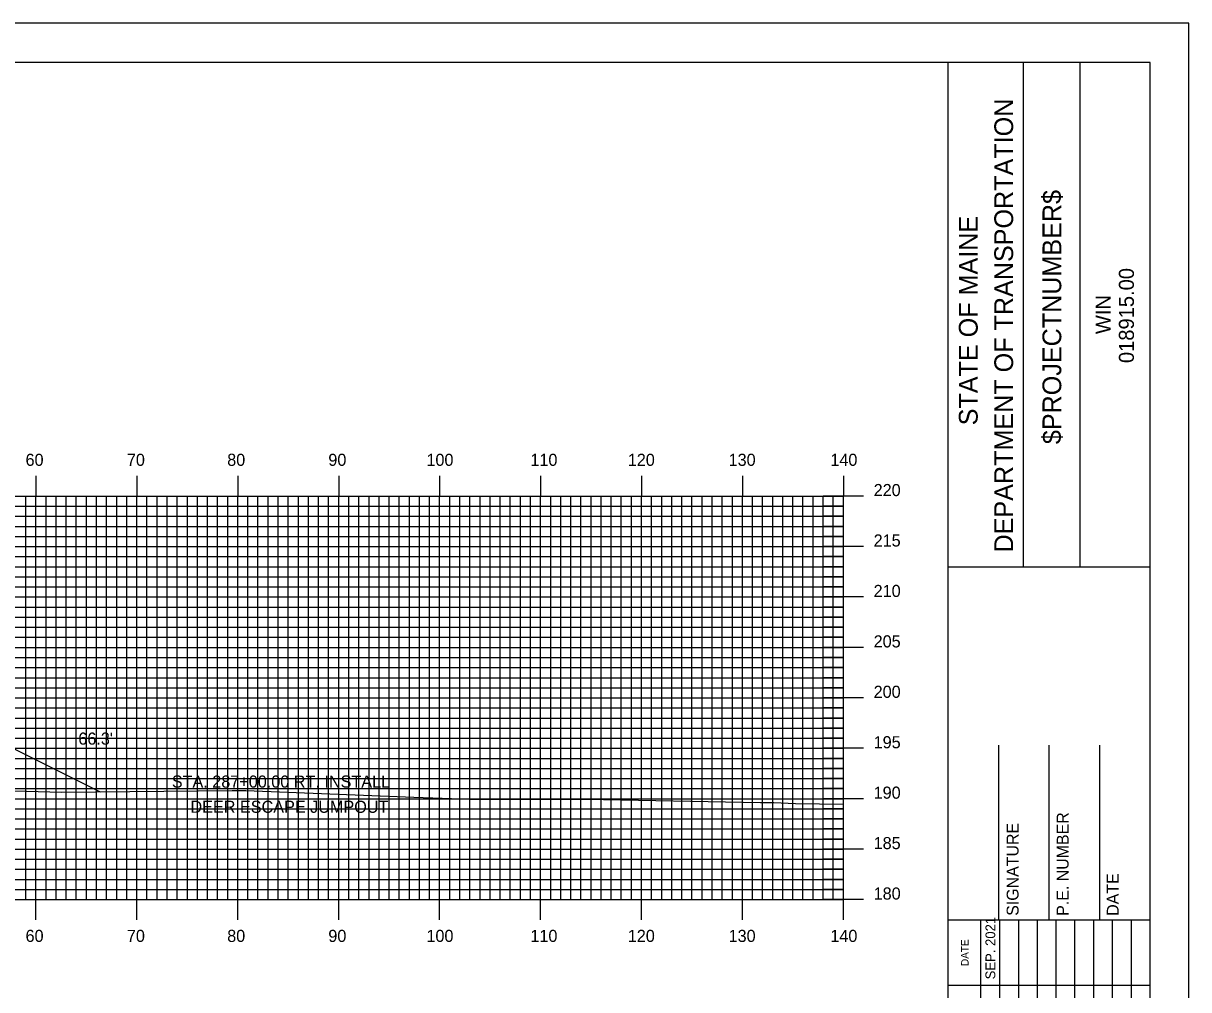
# Model space of a CAD drawing. Extents: x 1812554 to 1812897, y 442591 to 442811.
# Drawn here: x 1812778.7 to 1812894.2, y 442714.7 to 442810.5 of the extents above; entities that cross this region are included whole.
import ezdxf

# ---------------------------------------------------------------- set-up
doc = ezdxf.new("R2010")
doc.units = 0
for name, color, linetype in [('BORDER', 7, 'Continuous'), ('D_Roadway_Centerline', 7, 'Continuous'), ('D_Roadway_SlopeLines', 7, 'Continuous'), ('D_Text_Standard', 7, 'Continuous'), ('H_V ANNOTATION', 7, 'Continuous'), ('MAJOR', 7, 'Continuous'), ('MINOR', 7, 'Continuous'), ('PLOT BOUNDARY', 7, 'Continuous'), ('S_Roadway_Centerline', 7, 'Continuous')]:
    doc.layers.add(name, color=color, linetype=linetype)

msp = doc.modelspace()

# ---------------------------------------------------------------- linework, layer by layer
at = {"layer": 'BORDER'}
for p, q in [((1812870.34, 442596.67), (1812870.34, 442806.67)), ((1812877.8, 442756.66), (1812877.8, 442806.66)), ((1812883.39, 442756.66), (1812883.39, 442806.66)), ((1812870.34, 442756.65), (1812890.34, 442756.65)), ((1812875.34, 442721.67), (1812875.34, 442738.97)), ((1812880.34, 442721.67), (1812880.34, 442738.97)), ((1812885.34, 442721.67), (1812885.34, 442738.97)), ((1812870.34, 442721.67), (1812890.34, 442721.67))]:
    msp.add_line(p, q, dxfattribs=at)
msp.add_lwpolyline([(1812570.34, 442596.67), (1812890.34, 442596.67), (1812890.34, 442806.67), (1812570.34, 442806.67)], close=True, dxfattribs=at)
for points in [[(1812873.57, 442715.17), (1812873.57, 442721.67)], [(1812875.44, 442686.68), (1812875.44, 442721.67)], [(1812877.3, 442721.67), (1812877.3, 442686.68)], [(1812879.16, 442686.68), (1812879.16, 442721.67)], [(1812881.03, 442686.68), (1812881.03, 442721.67)], [(1812882.89, 442686.68), (1812882.89, 442721.67)], [(1812884.75, 442686.68), (1812884.75, 442721.67)], [(1812886.62, 442686.68), (1812886.62, 442721.67)], [(1812888.48, 442686.68), (1812888.48, 442721.67)], [(1812873.57, 442686.68), (1812873.57, 442720.26)], [(1812870.34, 442715.17), (1812890.34, 442715.17)]]:
    msp.add_lwpolyline(points, dxfattribs=at)
at = {"layer": 'D_Roadway_Centerline'}
msp.add_lwpolyline([(1812657.88, 442737.96), (1812691.73, 442754.88), (1812696.94, 442757.49), (1812699.94, 442757.55), (1812707.94, 442757.71), (1812719.94, 442757.13), (1812731.94, 442756.55), (1812739.94, 442756.17), (1812742.94, 442756.03), (1812748.47, 442753.26), (1812786.29, 442734.35)], dxfattribs=at)
at = {"layer": 'D_Roadway_SlopeLines'}
msp.add_lwpolyline([(1812742.94, 442756.03), (1812786.29, 442734.35)], dxfattribs=at)
at = {"layer": 'MAJOR'}
for p, q in [((1812779.94, 442765.67), (1812779.94, 442763.67)), ((1812789.94, 442765.67), (1812789.94, 442763.67)), ((1812799.94, 442765.67), (1812799.94, 442763.67)), ((1812809.94, 442765.67), (1812809.94, 442763.67)), ((1812819.94, 442765.67), (1812819.94, 442763.67)), ((1812829.94, 442765.67), (1812829.94, 442763.67)), ((1812839.94, 442765.67), (1812839.94, 442763.67)), ((1812849.94, 442765.67), (1812849.94, 442763.67)), ((1812859.94, 442765.67), (1812859.94, 442763.67)), ((1812579.94, 442763.67), (1812859.94, 442763.67)), ((1812579.94, 442763.67), (1812859.94, 442763.67)), ((1812779.94, 442723.67), (1812779.94, 442763.67)), ((1812789.94, 442723.67), (1812789.94, 442763.67)), ((1812799.94, 442723.67), (1812799.94, 442763.67)), ((1812809.94, 442723.67), (1812809.94, 442763.67)), ((1812819.94, 442723.67), (1812819.94, 442763.67)), ((1812829.94, 442723.67), (1812829.94, 442763.67)), ((1812839.94, 442723.67), (1812839.94, 442763.67)), ((1812849.94, 442723.67), (1812849.94, 442763.67)), ((1812861.95, 442763.67), (1812857.94, 442763.67)), ((1812859.94, 442723.67), (1812859.94, 442763.67)), ((1812859.94, 442723.67), (1812859.94, 442763.67)), ((1812579.94, 442758.67), (1812859.94, 442758.67)), ((1812861.95, 442758.67), (1812857.94, 442758.67)), ((1812579.94, 442753.67), (1812859.94, 442753.67)), ((1812861.95, 442753.67), (1812857.94, 442753.67)), ((1812579.94, 442748.67), (1812859.94, 442748.67)), ((1812861.95, 442748.67), (1812857.94, 442748.67)), ((1812579.94, 442743.67), (1812859.94, 442743.67)), ((1812861.95, 442743.67), (1812857.94, 442743.67)), ((1812579.94, 442738.67), (1812859.94, 442738.67)), ((1812861.95, 442738.67), (1812857.94, 442738.67)), ((1812579.94, 442733.67), (1812859.94, 442733.67)), ((1812861.95, 442733.67), (1812857.94, 442733.67)), ((1812579.94, 442728.67), (1812859.94, 442728.67)), ((1812861.95, 442728.67), (1812857.94, 442728.67)), ((1812579.94, 442723.67), (1812859.94, 442723.67)), ((1812579.94, 442723.67), (1812859.94, 442723.67)), ((1812779.94, 442721.66), (1812779.94, 442723.67)), ((1812789.94, 442721.66), (1812789.94, 442723.67)), ((1812799.94, 442721.66), (1812799.94, 442723.67)), ((1812809.94, 442721.66), (1812809.94, 442723.67)), ((1812819.94, 442721.66), (1812819.94, 442723.67)), ((1812829.94, 442721.66), (1812829.94, 442723.67)), ((1812839.94, 442721.66), (1812839.94, 442723.67)), ((1812849.94, 442721.66), (1812849.94, 442723.67)), ((1812861.95, 442723.67), (1812857.94, 442723.67)), ((1812859.94, 442721.66), (1812859.94, 442723.67))]:
    msp.add_line(p, q, dxfattribs=at)
at = {"layer": 'MINOR'}
for p, q in [((1812778.94, 442723.67), (1812778.94, 442763.67)), ((1812780.94, 442723.67), (1812780.94, 442763.67)), ((1812781.94, 442723.67), (1812781.94, 442763.67)), ((1812782.94, 442723.67), (1812782.94, 442763.67)), ((1812783.94, 442723.67), (1812783.94, 442763.67)), ((1812784.94, 442723.67), (1812784.94, 442763.67)), ((1812785.94, 442723.67), (1812785.94, 442763.67)), ((1812786.94, 442723.67), (1812786.94, 442763.67)), ((1812787.94, 442723.67), (1812787.94, 442763.67)), ((1812788.94, 442723.67), (1812788.94, 442763.67)), ((1812790.94, 442723.67), (1812790.94, 442763.67)), ((1812791.94, 442723.67), (1812791.94, 442763.67)), ((1812792.94, 442723.67), (1812792.94, 442763.67)), ((1812793.94, 442723.67), (1812793.94, 442763.67)), ((1812794.94, 442723.67), (1812794.94, 442763.67)), ((1812795.94, 442723.67), (1812795.94, 442763.67)), ((1812796.94, 442723.67), (1812796.94, 442763.67)), ((1812797.94, 442723.67), (1812797.94, 442763.67)), ((1812798.94, 442723.67), (1812798.94, 442763.67)), ((1812800.94, 442723.67), (1812800.94, 442763.67)), ((1812801.94, 442723.67), (1812801.94, 442763.67)), ((1812802.94, 442723.67), (1812802.94, 442763.67)), ((1812803.94, 442723.67), (1812803.94, 442763.67)), ((1812804.94, 442723.67), (1812804.94, 442763.67)), ((1812805.94, 442723.67), (1812805.94, 442763.67)), ((1812806.94, 442723.67), (1812806.94, 442763.67)), ((1812807.94, 442723.67), (1812807.94, 442763.67)), ((1812808.94, 442723.67), (1812808.94, 442763.67)), ((1812810.94, 442723.67), (1812810.94, 442763.67)), ((1812811.94, 442723.67), (1812811.94, 442763.67)), ((1812812.94, 442723.67), (1812812.94, 442763.67)), ((1812813.94, 442723.67), (1812813.94, 442763.67)), ((1812814.94, 442723.67), (1812814.94, 442763.67)), ((1812815.94, 442723.67), (1812815.94, 442763.67)), ((1812816.94, 442723.67), (1812816.94, 442763.67)), ((1812817.94, 442723.67), (1812817.94, 442763.67)), ((1812818.94, 442723.67), (1812818.94, 442763.67)), ((1812820.94, 442723.67), (1812820.94, 442763.67)), ((1812821.94, 442723.67), (1812821.94, 442763.67)), ((1812822.94, 442723.67), (1812822.94, 442763.67)), ((1812823.94, 442723.67), (1812823.94, 442763.67)), ((1812824.94, 442723.67), (1812824.94, 442763.67)), ((1812825.94, 442723.67), (1812825.94, 442763.67)), ((1812826.94, 442723.67), (1812826.94, 442763.67)), ((1812827.94, 442723.67), (1812827.94, 442763.67)), ((1812828.94, 442723.67), (1812828.94, 442763.67)), ((1812830.94, 442723.67), (1812830.94, 442763.67)), ((1812831.94, 442723.67), (1812831.94, 442763.67)), ((1812832.94, 442723.67), (1812832.94, 442763.67)), ((1812833.94, 442723.67), (1812833.94, 442763.67)), ((1812834.94, 442723.67), (1812834.94, 442763.67)), ((1812835.94, 442723.67), (1812835.94, 442763.67)), ((1812836.94, 442723.67), (1812836.94, 442763.67)), ((1812837.94, 442723.67), (1812837.94, 442763.67)), ((1812838.94, 442723.67), (1812838.94, 442763.67)), ((1812840.94, 442723.67), (1812840.94, 442763.67)), ((1812841.94, 442723.67), (1812841.94, 442763.67)), ((1812842.94, 442723.67), (1812842.94, 442763.67)), ((1812843.94, 442723.67), (1812843.94, 442763.67)), ((1812844.94, 442723.67), (1812844.94, 442763.67)), ((1812845.94, 442723.67), (1812845.94, 442763.67)), ((1812846.94, 442723.67), (1812846.94, 442763.67)), ((1812847.94, 442723.67), (1812847.94, 442763.67)), ((1812848.94, 442723.67), (1812848.94, 442763.67)), ((1812850.94, 442723.67), (1812850.94, 442763.67)), ((1812851.94, 442723.67), (1812851.94, 442763.67)), ((1812852.94, 442723.67), (1812852.94, 442763.67)), ((1812853.94, 442723.67), (1812853.94, 442763.67)), ((1812854.94, 442723.67), (1812854.94, 442763.67)), ((1812855.94, 442723.67), (1812855.94, 442763.67)), ((1812856.94, 442723.67), (1812856.94, 442763.67)), ((1812857.94, 442723.67), (1812857.94, 442763.67)), ((1812858.94, 442723.67), (1812858.94, 442763.67)), ((1812579.94, 442762.67), (1812859.94, 442762.67)), ((1812859.94, 442762.67), (1812857.94, 442762.67)), ((1812579.94, 442761.67), (1812859.94, 442761.67)), ((1812859.94, 442761.67), (1812857.94, 442761.67)), ((1812579.94, 442760.67), (1812859.94, 442760.67)), ((1812859.94, 442760.67), (1812857.94, 442760.67)), ((1812579.94, 442759.67), (1812859.94, 442759.67)), ((1812859.94, 442759.67), (1812857.94, 442759.67)), ((1812579.94, 442757.67), (1812859.94, 442757.67)), ((1812859.94, 442757.67), (1812857.94, 442757.67)), ((1812579.94, 442756.67), (1812859.94, 442756.67)), ((1812859.94, 442756.67), (1812857.94, 442756.67)), ((1812579.94, 442755.67), (1812859.94, 442755.67)), ((1812859.94, 442755.67), (1812857.94, 442755.67)), ((1812579.94, 442754.67), (1812859.94, 442754.67)), ((1812859.94, 442754.67), (1812857.94, 442754.67)), ((1812579.94, 442752.67), (1812859.94, 442752.67)), ((1812579.94, 442751.67), (1812859.94, 442751.67)), ((1812859.94, 442752.67), (1812857.94, 442752.67)), ((1812859.94, 442751.67), (1812857.94, 442751.67)), ((1812579.94, 442750.67), (1812859.94, 442750.67)), ((1812859.94, 442750.67), (1812857.94, 442750.67)), ((1812579.94, 442749.67), (1812859.94, 442749.67)), ((1812859.94, 442749.67), (1812857.94, 442749.67)), ((1812579.94, 442747.67), (1812859.94, 442747.67)), ((1812859.94, 442747.67), (1812857.94, 442747.67)), ((1812579.94, 442746.67), (1812859.94, 442746.67)), ((1812859.94, 442746.67), (1812857.94, 442746.67)), ((1812579.94, 442745.67), (1812859.94, 442745.67)), ((1812859.94, 442745.67), (1812857.94, 442745.67)), ((1812579.94, 442744.67), (1812859.94, 442744.67)), ((1812859.94, 442744.67), (1812857.94, 442744.67)), ((1812579.94, 442742.67), (1812859.94, 442742.67)), ((1812859.94, 442742.67), (1812857.94, 442742.67)), ((1812579.94, 442741.67), (1812859.94, 442741.67)), ((1812859.94, 442741.67), (1812857.94, 442741.67)), ((1812579.94, 442740.67), (1812859.94, 442740.67)), ((1812859.94, 442740.67), (1812857.94, 442740.67)), ((1812579.94, 442739.67), (1812859.94, 442739.67)), ((1812859.94, 442739.67), (1812857.94, 442739.67)), ((1812579.94, 442737.67), (1812859.94, 442737.67)), ((1812579.94, 442736.67), (1812859.94, 442736.67)), ((1812859.94, 442737.67), (1812857.94, 442737.67)), ((1812859.94, 442736.67), (1812857.94, 442736.67)), ((1812579.94, 442735.67), (1812859.94, 442735.67)), ((1812859.94, 442735.67), (1812857.94, 442735.67)), ((1812579.94, 442734.67), (1812859.94, 442734.67)), ((1812859.94, 442734.67), (1812857.94, 442734.67)), ((1812579.94, 442732.67), (1812859.94, 442732.67)), ((1812859.94, 442732.67), (1812857.94, 442732.67)), ((1812579.94, 442731.67), (1812859.94, 442731.67)), ((1812859.94, 442731.67), (1812857.94, 442731.67)), ((1812579.94, 442730.67), (1812859.94, 442730.67)), ((1812859.94, 442730.67), (1812857.94, 442730.67)), ((1812579.94, 442729.67), (1812859.94, 442729.67)), ((1812859.94, 442729.67), (1812857.94, 442729.67)), ((1812579.94, 442727.67), (1812859.94, 442727.67)), ((1812859.94, 442727.67), (1812857.94, 442727.67)), ((1812579.94, 442726.67), (1812859.94, 442726.67)), ((1812859.94, 442726.67), (1812857.94, 442726.67)), ((1812579.94, 442725.67), (1812859.94, 442725.67)), ((1812859.94, 442725.67), (1812857.94, 442725.67)), ((1812579.94, 442724.67), (1812859.94, 442724.67)), ((1812859.94, 442724.67), (1812857.94, 442724.67))]:
    msp.add_line(p, q, dxfattribs=at)
at = {"layer": 'PLOT BOUNDARY'}
msp.add_lwpolyline([(1812554.16, 442590.55), (1812894.16, 442590.55), (1812894.16, 442810.55), (1812554.16, 442810.55)], close=True, dxfattribs=at)
at = {"layer": 'S_Roadway_Centerline'}
msp.add_lwpolyline([(1812773.23, 442734.57), (1812782.47, 442734.32), (1812799.39, 442734.48), (1812800.25, 442734.49), (1812800.74, 442734.5), (1812817.37, 442733.81), (1812823.91, 442733.58), (1812834.44, 442733.62), (1812851.73, 442733.3), (1812853.06, 442733.28), (1812855.19, 442733.21), (1812859.94, 442733.12)], dxfattribs=at)

# ---------------------------------------------------------------- texts
at = {"layer": 'BORDER'}
for s, height, p in [('DEPARTMENT OF TRANSPORTATION', 1.8635, (1812876.76, 442758.08)), ('$PROJECTNUMBER$', 1.8635, (1812881.53, 442768.82)), ('STATE OF MAINE', 1.8635, (1812873.25, 442770.69)), ('018915.00', 1.491, (1812888.73, 442776.86)), ('WIN', 1.491, (1812886.42, 442779.73)), ('P.E. NUMBER', 1.1811, (1812882.26, 442722.06)), ('SIGNATURE', 1.181, (1812877.3, 442722.06)), ('DATE', 1.181, (1812887.22, 442722.06)), ('SEP. 2021', 0.969, (1812874.99, 442715.76)), ('DATE', 0.743, (1812872.35, 442717.08))]:
    msp.add_text(s, height=height, rotation=90, dxfattribs=at).set_placement(p)
at = {"layer": 'D_Text_Standard'}
for s, p in [("66.3'", (1812784.14, 442739.03)), ('STA. 287+00.00 RT. INSTALL ', (1812793.4, 442734.77)), ('DEER ESCAPE JUMPOUT', (1812795.25, 442732.27))]:
    msp.add_text(s, height=1.2, dxfattribs=at).set_placement(p)
at = {"layer": 'H_V ANNOTATION'}
for s, p in [('60', (1812778.91, 442766.67)), ('70', (1812788.95, 442766.67)), ('80', (1812798.89, 442766.67)), ('90', (1812808.91, 442766.67)), ('100', (1812818.63, 442766.67)), ('110', (1812828.93, 442766.67)), ('120', (1812838.58, 442766.67)), ('130', (1812848.57, 442766.67)), ('140', (1812858.65, 442766.67)), ('220', (1812862.94, 442763.67)), ('215', (1812862.94, 442758.67)), ('210', (1812862.94, 442753.67)), ('205', (1812862.94, 442748.67)), ('200', (1812862.94, 442743.67)), ('195', (1812862.94, 442738.67)), ('190', (1812862.94, 442733.67)), ('185', (1812862.94, 442728.67)), ('180', (1812862.94, 442723.67)), ('60', (1812778.91, 442719.47)), ('70', (1812788.95, 442719.47)), ('80', (1812798.89, 442719.47)), ('90', (1812808.91, 442719.47)), ('100', (1812818.63, 442719.47)), ('110', (1812828.93, 442719.47)), ('120', (1812838.58, 442719.47)), ('130', (1812848.57, 442719.47)), ('140', (1812858.65, 442719.47))]:
    msp.add_text(s, height=1.2, dxfattribs=at).set_placement(p)

doc.saveas('drawing.dxf')
